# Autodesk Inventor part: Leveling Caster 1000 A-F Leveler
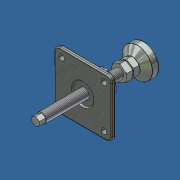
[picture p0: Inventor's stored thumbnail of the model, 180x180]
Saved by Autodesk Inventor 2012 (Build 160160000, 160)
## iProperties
Created: 2015-01
Part Number: Leveling Caster 1000 A-F Leveler
Material: Default
Document SubType Name: Modeling
Designer: Admin
Density: 1 g/cm^3
Author: Admin
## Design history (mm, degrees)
feature "Base1"
sketch "Sketch1"
  geometry: C1 r 9.5 at (0, 0) reference; C2 r 25 at (0, 0); 1 further point
  constraints: 1 centre point, 1 coincident
  dimensions: "d0" = 50 diameter of C2
extrude "Extrusion1" join sketch "Sketch1" distance "d1" = 15; taper "d2" = 0 deg
sketch "Sketch2"
  geometry: C1 r 25 at (0, 0) reference; C2 r 9.5 at (0, 0) reference; 1 further point
extrude "Extrusion2" join sketch "Sketch2" distance "d3" = 5; taper "d4" = 0 deg
fillet "Fillet1" dims "d5" = 2
chamfer "Chamfer1" distance "d6" = 12; stored, may be unused: second distance "d7" = 2, angle "d8" = 35 deg
fillet "Fillet2" dims "d9" = 0.5
body "Solid1"
